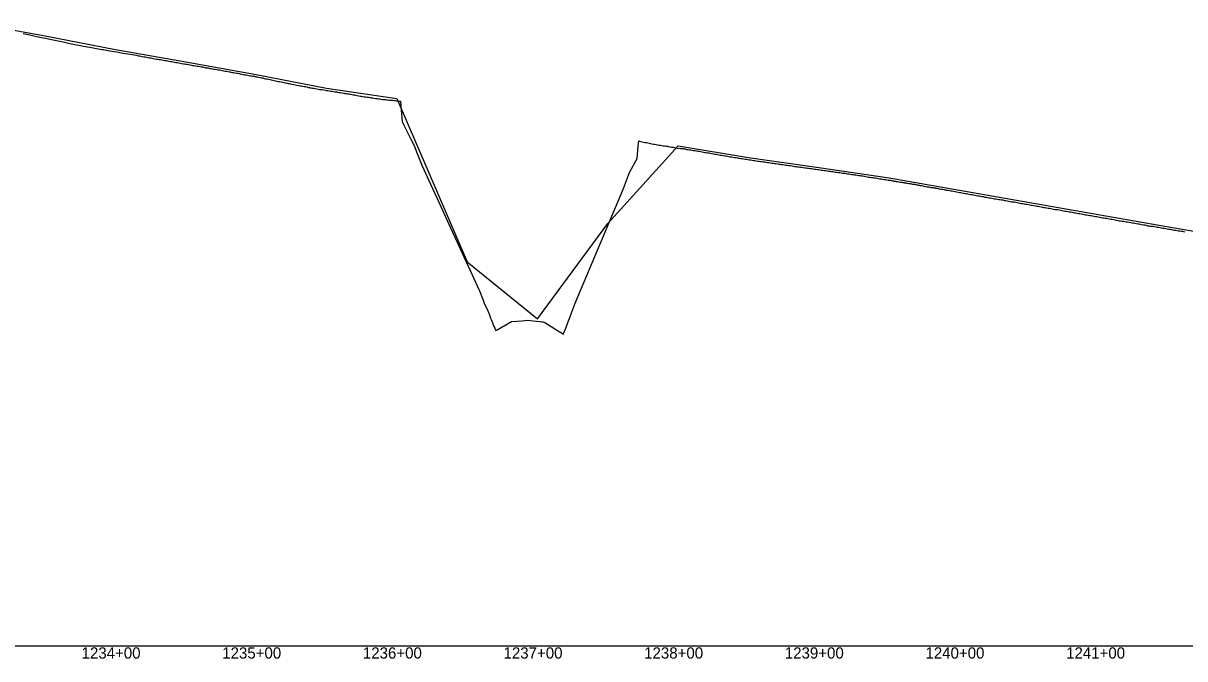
# Model space of a CAD drawing. Extents: x -3793 to 50787, y -1075 to 6138.
# Drawn here: x 10712 to 11538, y 2991 to 3442 of the extents above; entities that cross this region are included whole.
import ezdxf

# ---------------------------------------------------------------- set-up
doc = ezdxf.new("R2010")
doc.units = 0
for name, color, linetype in [('RD_DDB_Profile_EX', 7, 'Continuous'), ('RD_DDB_Profile_PR', 7, 'Continuous'), ('RD_DDB_StaTX', 7, 'Continuous'), ('RD_GPK_Profile_Cell', 7, 'Continuous')]:
    doc.layers.add(name, color=color, linetype=linetype)

msp = doc.modelspace()

# ---------------------------------------------------------------- linework, layer by layer
at = {"layer": 'RD_DDB_Profile_EX'}
for points in [[(10711.5226, 3435.037695), (10716.272076, 3434.033025), (10721.021552, 3433.02714), (10725.771029, 3432.020045), (10727.701013, 3431.648155), (10730.520505, 3431.05129), (10735.269982, 3430.04314), (10740.019458, 3429.03227), (10744.768934, 3428.01868), (10749.518411, 3427.00238), (10752.414609, 3426.418435), (10754.267887, 3426.09926), (10759.017363, 3425.277585), (10763.76684, 3424.452205), (10767.862399, 3423.713405), (10768.516316, 3423.602885), (10773.265792, 3422.797305), (10778.015269, 3421.98886), (10782.764745, 3421.17755), (10787.514221, 3420.36338), (10792.30311, 3419.57975), (10793.299339, 3419.285795), (10794.299228, 3419.14256), (10795.303154, 3418.943025), (10796.30302, 3418.74236), (10797.299199, 3418.58722), (10798.299138, 3418.43557), (10799.302349, 3418.18956), (10800.302281, 3417.99978), (10801.306182, 3417.80405), (10801.76265, 3417.758265), (10802.296945, 3417.704175), (10803.300912, 3417.483735), (10804.300165, 3417.34362), (10805.299063, 3417.053465), (10806.512127, 3416.93618), (10807.293775, 3416.84868), (10808.296695, 3416.689405), (10809.295635, 3416.499), (10810.299296, 3416.34801), (10811.289227, 3416.143485), (10812.292583, 3415.98803), (10813.291601, 3415.792745), (10814.293861, 3415.587365), (10815.29287, 3415.44605), (10816.287852, 3415.238785), (10817.285493, 3415.13517), (10818.288555, 3414.937095), (10819.28689, 3414.698905), (10820.236153, 3414.553075), (10820.760556, 3414.47179), (10821.232904, 3414.39124), (10822.230999, 3414.144775), (10823.222926, 3413.95443), (10824.221468, 3413.84666), (10825.510032, 3413.58003), (10826.221282, 3413.40868), (10827.21984, 3413.303775), (10828.219735, 3413.15324), (10829.225637, 3413.00416), (10830.259509, 3412.83919), (10831.2229, 3412.652015), (10832.215968, 3412.415745), (10833.215832, 3412.255615), (10834.221707, 3412.15596), (10835.214283, 3411.920275), (10836.219608, 3411.81587), (10837.219989, 3411.568015), (10838.218037, 3411.41629), (10839.217698, 3411.3046), (10839.758461, 3411.168325), (10840.215748, 3411.061815), (10841.215574, 3410.736265), (10842.215949, 3410.633465), (10843.213991, 3410.562915), (10844.507938, 3410.30062), (10845.219663, 3410.122675), (10846.212225, 3410.01766), (10847.217354, 3409.7752), (10848.209908, 3409.6658), (10849.257414, 3409.500895), (10850.215579, 3409.36089)], [(10850.215579, 3409.36089), (10851.208125, 3409.159955), (10852.213972, 3408.91263), (10853.213797, 3408.772075), (10854.211838, 3408.60583), (10855.211503, 3408.364145), (10856.204026, 3408.26264), (10857.209885, 3408.002185), (10858.20972, 3407.852405), (10858.756367, 3407.768325), (10859.207769, 3407.69868), (10860.208089, 3407.40217), (10861.213499, 3407.253535), (10862.20598, 3407.097785), (10863.505843, 3406.92422), (10864.203749, 3406.789215), (10865.204045, 3406.55249), (10865.999784, 3406.4476), (10867.057171, 3406.27399), (10868.255319, 3405.95116), (10868.979874, 3405.71299), (10869.981382, 3405.658365), (10871.057632, 3405.35229), (10871.977767, 3405.263525), (10873.061131, 3405.10046), (10874.065337, 3404.92293), (10874.981471, 3404.696475), (10876.064321, 3404.638615), (10876.977635, 3404.367665), (10877.972417, 3404.16866), (10878.973787, 3404.00678), (10880.062261, 3403.752835), (10880.970699, 3403.61878), (10881.972038, 3403.456255), (10882.503748, 3403.269245), (10883.063689, 3403.10206), (10883.968386, 3402.96807), (10885.061111, 3402.83864), (10885.96452, 3402.56961), (10887.253225, 3402.341515), (10887.960651, 3402.205725), (10889.056201, 3401.975375), (10889.957593, 3401.70641), (10890.958873, 3401.541925), (10892.055873, 3401.23155), (10892.955822, 3401.05243), (10893.95595, 3400.855115), (10895.057622, 3400.63565), (10896.05179, 3400.43008), (10896.953578, 3400.25052), (10897.954863, 3400.090495), (10898.43082, 3400), (10899.200461, 3399.766405), (10899.980789, 3399.649735), (10900.756284, 3399.49272), (10901.537873, 3399.37586), (10901.947913, 3399.288625), (10902.942719, 3399.16792), (10903.944035, 3398.882175), (10905.321318, 3398.572545), (10906.289417, 3398.434385), (10907.285695, 3398.18517), (10908.286228, 3397.993515), (10909.290089, 3397.890085), (10910.286909, 3397.696015), (10911.286863, 3397.4883), (10912.291126, 3397.30064), (10913.287248, 3397.09546), (10914.287728, 3396.80391), (10915.283841, 3396.615925), (10915.750083, 3396.570505), (10916.288006, 3396.487835), (10917.287768, 3396.25202), (10918.284402, 3396.145925), (10919.287844, 3395.95293), (10920.499559, 3395.674865), (10921.284159, 3395.517355), (10922.288121, 3395.367915), (10923.279311, 3395.25027), (10924.284325, 3395.157155), (10925.287587, 3395.00146), (10926.279366, 3394.83922), (10927.283602, 3394.65242), (10928.287439, 3394.49617), (10929.283221, 3394.31484), (10930.282738, 3394.12304), (10931.286477, 3393.97289), (10932.282174, 3393.80914), (10933.282317, 3393.710355), (10934.278008, 3393.50955), (10934.747988, 3393.46299), (10935.281708, 3393.402845), (10936.281067, 3393.24738), (10937.277375, 3393.059105), (10938.280349, 3392.921685), (10939.497465, 3392.70068), (10940.275954, 3392.490415), (10941.279549, 3392.426855), (10942.271456, 3392.23316), (10943.275053, 3392.08234), (10944.277978, 3391.956635)], [(10944.277978, 3391.956635), (10945.27047, 3391.68115), (10946.273334, 3391.574015), (10947.276886, 3391.422945), (10948.125354, 3391.223745), (10949.124194, 3391.036385), (10950.122287, 3390.855175), (10951.148796, 3390.59418), (10952.148343, 3390.44546), (10953.142979, 3390.32913), (10954.142482, 3390.09315), (10955.141247, 3389.994275), (10956.140658, 3389.875385), (10957.148192, 3389.713985), (10958.147617, 3389.57145), (10958.49537, 3389.501975), (10959.146274, 3389.372215), (10960.145539, 3389.265875), (10961.139915, 3389.1315), (10962.146749, 3388.939905), (10963.244846, 3388.77369), (10964.145717, 3388.676975), (10965.14415, 3388.54154), (10966.143276, 3388.39177), (10967.149238, 3388.26466), (10968.148342, 3388.222045), (10969.146607, 3388.136565), (10970.142673, 3388.010195), (10971.140938, 3387.99669), (10972.147425, 3387.81277), (10973.145623, 3387.75551), (10974.14443, 3387.69941), (10975.142528, 3387.48992), (10976.142609, 3387.381435), (10977.148226, 3387.203235), (10977.493275, 3387.1688), (10978.142782, 3387.104045), (10979.140709, 3387.06081), (10979.998327, 3387.024545), (10980.478464, 3380.58499), (10980.995674, 3372.54904), (10982.242752, 3370.042175), (10986.992228, 3360.49365), (10989.273855, 3355.906035), (10991.741705, 3349.777605), (10995.093873, 3341.451325), (10996.491181, 3338.414105), (11001.240657, 3328.08981), (11005.990134, 3317.764805), (11010.73961, 3307.439125), (11015.489086, 3297.112795), (11020.238563, 3286.78585), (11024.988039, 3276.45831), (11029.737515, 3266.130215), (11034.486992, 3255.801585), (11036.158402, 3252.166615), (11038.785117, 3245.509115), (11039.236468, 3244.248405), (11039.723685, 3242.888265), (11040.757161, 3240.529295), (11041.868532, 3238.03651), (11043.09915, 3235.14413), (11043.985944, 3232.84878), (11044.353961, 3231.89664), (11045.337396, 3229.568125), (11046.313644, 3226.949935), (11046.96272, 3225.75562), (11047.750403, 3224.08031), (11048.735421, 3224.659325), (11052.713079, 3226.998465), (11053.484897, 3227.4145), (11056.083854, 3228.815255), (11058.928951, 3230.36871), (11062.518094, 3230.696995), (11066.057082, 3231.0213), (11068.206228, 3231.208645), (11070.404375, 3231.419235), (11074.150154, 3230.998715), (11079.0208, 3230.45052), (11080.237702, 3230.313655), (11081.180516, 3230.20771), (11082.440301, 3229.869885), (11089.630611, 3225.29527), (11095.721485, 3221.48838), (11096.089507, 3222.43014), (11097.446264, 3225.824595), (11098.664693, 3229.068585), (11099.788999, 3232.04427), (11103.424789, 3241.514595), (11104.174874, 3243.540475), (11138.549471, 3324.95213), (11142.802066, 3336.407525), (11148.165449, 3346.339715), (11148.874291, 3354.928305), (11149.230024, 3358.743785), (11149.561851, 3358.646965), (11150.691356, 3358.433315), (11151.690668, 3358.183495), (11152.693441, 3357.896705), (11153.684135, 3357.706675), (11154.688151, 3357.576625)], [(11154.688151, 3357.576625), (11155.687467, 3357.39685), (11156.689704, 3357.240055), (11157.684389, 3356.89625), (11158.684944, 3356.64655), (11159.687186, 3356.533165), (11160.553298, 3356.35998), (11161.682409, 3356.24625), (11162.681208, 3356.009885), (11163.551638, 3355.83608), (11164.678636, 3355.676225), (11165.678671, 3355.50288), (11166.681439, 3355.372405), (11167.548557, 3355.24261), (11168.675414, 3355.015495), (11169.675456, 3354.92924), (11170.546896, 3354.79856), (11171.672856, 3354.51505), (11172.671673, 3354.315525), (11173.675664, 3354.26531), (11174.543814, 3354.048455), (11175.669112, 3353.95206), (11176.668449, 3353.71309), (11177.672436, 3353.45219), (11178.540733, 3353.495895), (11178.863948, 3353.479455), (11179.71095, 3353.30824), (11180.568666, 3353.265185), (11181.303162, 3353.11465), (11182.307317, 3353.01467), (11183.298534, 3352.7), (11184.301413, 3352.585265), (11185.305571, 3352.49262), (11186.304188, 3352.4), (11187.300959, 3352.170315), (11188.299591, 3352.027495), (11189.301702, 3351.88496), (11190.298487, 3351.785035), (11191.297115, 3351.492435), (11192.301285, 3351.362105), (11193.299912, 3351.15), (11194.295396, 3351.05), (11195.299569, 3350.84237), (11196.298201, 3350.634565), (11197.301037, 3350.484555), (11198.292897, 3350.32665), (11199.295725, 3350.18442), (11200.299907, 3349.942195), (11201.298534, 3349.718415), (11202.387926, 3349.57648), (11203.388252, 3349.37625), (11204.390252, 3349.31841), (11205.393751, 3349.152665), (11206.386102, 3348.902535), (11207.38869, 3348.73425), (11208.389038, 3348.568185), (11209.392536, 3348.426165), (11210.386531, 3348.23426), (11211.386894, 3348.034105), (11212.39039, 3347.88412), (11213.381839, 3347.760325), (11214.385333, 3347.55244), (11215.388825, 3347.41041), (11216.387705, 3347.252075), (11217.38318, 3347.068315), (11218.383597, 3346.90999), (11219.385564, 3346.76807), (11220.229469, 3346.6), (11220.870179, 3346.56812), (11221.869667, 3346.367795), (11222.867744, 3346.17563), (11223.867242, 3345.97538), (11224.866753, 3345.866835), (11225.864811, 3345.69982), (11226.865155, 3345.51628), (11227.864696, 3345.38297), (11228.866784, 3345.224505), (11229.866321, 3345.07425), (11230.865871, 3344.906645), (11231.8639, 3344.815015), (11232.863462, 3344.60583), (11233.871105, 3344.432075), (11234.869105, 3344.33192), (11235.868687, 3344.222615), (11236.868283, 3344.08156), (11237.870234, 3343.940795), (11238.869826, 3343.790705), (11239.870342, 3343.690635), (11240.868312, 3343.53111), (11241.867936, 3343.34046), (11242.827964, 3343.15), (11243.828254, 3343.059665), (11244.826916, 3342.880555), (11245.825578, 3342.8), (11246.82424, 3342.60984), (11247.826118, 3342.5), (11248.826444, 3342.320305), (11249.825104, 3342.190045), (11250.823764, 3342.05), (11251.822424, 3341.91007), (11252.821083, 3341.779745)], [(11252.821083, 3341.779745), (11253.828223, 3341.620525), (11254.826883, 3341.46032), (11255.824439, 3341.35), (11256.827306, 3341.2), (11258.271562, 3340.989525), (11259.271035, 3340.8), (11260.270507, 3340.66059), (11261.26998, 3340.489355), (11262.269452, 3340.35), (11263.270981, 3340.23922), (11264.269672, 3340.06741), (11265.269152, 3340.01092), (11266.268631, 3339.88902), (11267.275539, 3339.738905), (11268.275008, 3339.55), (11269.276617, 3339.47754), (11270.276097, 3339.37742), (11271.275576, 3339.2), (11272.274219, 3339.05), (11273.273695, 3338.95), (11274.275377, 3338.761565), (11275.274863, 3338.65), (11276.27435, 3338.45), (11277.273836, 3338.338255), (11278.273322, 3338.2764), (11279.275079, 3338.01188), (11280.281852, 3337.87399), (11281.280458, 3337.786245), (11282.27994, 3337.66214), (11283.282189, 3337.47578), (11284.283994, 3337.375625), (11285.283483, 3337.313265), (11286.287691, 3337.11297), (11287.28631, 3336.97514), (11288.288215, 3336.8), (11289.286832, 3336.662205), (11290.287873, 3336.51271), (11291.28648, 3336.4256), (11292.28847, 3336.28712), (11293.296682, 3336.1), (11294.295269, 3335.91314), (11295.296387, 3335.786745), (11295.706357, 3335.75), (11296.702402, 3335.56321), (11297.70228, 3335.439975), (11298.705759, 3335.31335), (11299.70462, 3335.2), (11300.704521, 3334.963525), (11301.705629, 3334.827065), (11302.699162, 3334.72718), (11303.70159, 3334.55), (11304.701506, 3334.45), (11305.701441, 3334.2914), (11306.702497, 3334.127615), (11307.703786, 3333.95557), (11308.704824, 3333.8417), (11309.698455, 3333.641885), (11310.701927, 3333.44198), (11311.700801, 3333.30623), (11312.700777, 3333.06418), (11313.701759, 3333.02838), (11314.703124, 3332.79284), (11315.697828, 3332.67114), (11316.697823, 3332.52178), (11317.70129, 3332.421955), (11318.70017, 3332.23674), (11319.70019, 3332.09376), (11320.701094, 3331.908395), (11321.70111, 3331.79419), (11322.697231, 3331.55856), (11323.697271, 3331.42955), (11324.700734, 3331.329625), (11325.699621, 3331.194645), (11326.699688, 3330.96007), (11327.700509, 3330.860125), (11328.398137, 3330.755555), (11328.727924, 3330.695325), (11329.7239, 3330.44505), (11330.421897, 3330.340395), (11330.724297, 3330.234955), (11331.72652, 3330.080035), (11332.424528, 3329.975325), (11333.018039, 3329.940345), (11333.319138, 3329.880155), (11334.016473, 3329.775635), (11334.319858, 3329.73021), (11335.314757, 3329.53994), (11336.013378, 3329.434935), (11336.314595, 3329.45), (11337.015833, 3329.24021), (11337.316486, 3329.19517), (11338.014271, 3329.125525), (11338.316319, 3329.08025), (11339.016724, 3328.94046), (11339.319099, 3328.88011), (11340.011169, 3328.775205), (11340.311938, 3328.7), (11341.310819, 3328.56999), (11342.009598, 3328.43011), (11342.310648, 3328.415075)], [(11342.310648, 3328.415075), (11343.012061, 3328.310105), (11343.312543, 3328.219905), (11344.004769, 3328.080065), (11344.306261, 3328.06501), (11345.308154, 3327.935015), (11346.007394, 3327.76013), (11346.307993, 3327.7), (11347.009857, 3327.59501), (11347.309885, 3327.55), (11348.008282, 3327.4103), (11348.30972, 3327.365095), (11349.005027, 3327.259925), (11349.305482, 3327.17008), (11350.005187, 3327.06501), (11350.305332, 3327.03497), (11351.307221, 3326.854995), (11352.00608, 3326.54031), (11352.307066, 3326.525365), (11353.004508, 3326.45586), (11353.307794, 3326.35), (11354.302664, 3326.219985), (11355.001418, 3326.15), (11355.302523, 3326.11984), (11356.003876, 3325.945085), (11356.304405, 3325.91505), (11357.002307, 3325.7057), (11357.304261, 3325.660485), (11357.999044, 3325.62503), (11358.299989, 3325.594955), (11358.99921, 3325.52517), (11359.299859, 3325.465055), (11360.001669, 3325.36002), (11360.301738, 3325.269945), (11361.000104, 3325.130155), (11361.301604, 3325.0849), (11362.002562, 3325.01505), (11362.303483, 3324.96986), (11362.995274, 3324.690325), (11363.297188, 3324.66013), (11364.299064, 3324.49501), (11364.997899, 3324.42527), (11365.29894, 3324.365075), (11366.297795, 3324.21502), (11366.990607, 3324.11001), (11367.290629, 3324.034975), (11367.993075, 3323.82487), (11368.29337, 3323.76495), (11369.193142, 3323.684985), (11370.194703, 3323.514875), (11371.192429, 3323.385125), (11372.189034, 3323.179475), (11373.186775, 3323.029475), (11374.187253, 3322.8), (11375.28425, 3322.59362), (11376.282005, 3322.320915), (11377.282798, 3322.17889), (11378.276693, 3322.043225), (11379.277501, 3321.828625), (11380.275278, 3321.664315), (11381.277354, 3321.320895), (11382.277735, 3321.36421), (11383.272049, 3321.106195), (11384.269851, 3320.928105), (11385.273311, 3320.763985), (11386.272322, 3320.6), (11387.266653, 3320.427585), (11388.267001, 3320.277645), (11389.267946, 3320.07746), (11390.265778, 3319.80494), (11391.263786, 3319.740695), (11392.261634, 3319.53643), (11393.259481, 3319.204315), (11394.26049, 3319.176975), (11395.260802, 3318.85407), (11396.256321, 3318.75), (11397.254191, 3318.636665), (11398.257666, 3318.40307), (11399.255541, 3318.25), (11400.249921, 3318.136875), (11401.250201, 3317.88946), (11402.252432, 3317.678185), (11403.250329, 3317.56304), (11404.253817, 3317.4), (11405.244981, 3317.22584), (11406.246128, 3317.024335), (11407.245164, 3316.9), (11408.24866, 3316.8), (11409.239809, 3316.50076), (11410.241007, 3316.32521), (11411.241232, 3316.187905), (11412.270572, 3316.06251), (11413.262888, 3315.82503), (11414.263934, 3315.537), (11415.264213, 3315.47492), (11416.265277, 3315.362375), (11417.265549, 3315.174815), (11418.259658, 3314.89904), (11419.314207, 3314.79913), (11420.305281, 3314.61223), (11421.307684, 3314.398795)], [(11421.307684, 3314.398795), (11422.305665, 3314.236635), (11423.309122, 3314.09859), (11424.300189, 3313.84839), (11425.30364, 3313.712035), (11426.301637, 3313.6), (11427.305094, 3313.311985), (11428.303095, 3313.161995), (11429.29858, 3313.023805), (11430.296589, 3312.861915), (11431.300052, 3312.597405), (11432.298064, 3312.485595), (11433.294557, 3312.28522), (11434.29473, 3312.161775), (11435.296045, 3311.985075), (11436.29621, 3311.785175), (11437.28954, 3311.56161), (11438.289698, 3311.461645), (11439.291045, 3311.31156), (11440.291196, 3311.034785), (11441.285537, 3310.911455), (11442.285681, 3310.77297), (11443.287058, 3310.538595), (11444.287195, 3310.32288), (11445.287601, 3310.145545), (11446.280691, 3310.034075), (11447.282098, 3309.91128), (11448.282221, 3309.722625), (11449.280283, 3309.538675), (11450.276694, 3309.283615), (11451.274767, 3308.98976), (11452.278239, 3308.92232), (11453.275344, 3308.7612), (11454.271744, 3308.62216), (11455.382957, 3308.45), (11456.385126, 3308.261085), (11457.384879, 3308.144265), (11458.38774, 3307.922405), (11459.158416, 3307.65), (11459.929866, 3307.561015), (11460.932525, 3307.46098), (11461.931425, 3307.28896), (11462.927222, 3307.15), (11463.930938, 3306.87177), (11464.929843, 3306.72811), (11465.925625, 3306.471695), (11466.928297, 3306.35), (11467.928245, 3306.260845), (11468.924011, 3306.042995), (11469.924807, 3305.82861), (11470.916795, 3305.689305), (11471.919483, 3305.471315), (11472.9232, 3305.181785), (11473.915171, 3305.08178), (11474.917865, 3304.95), (11475.920567, 3304.73948), (11476.912524, 3304.6), (11477.916231, 3304.410455), (11478.911961, 3304.14142), (11479.910879, 3304.08125), (11480.913588, 3303.91038), (11481.909313, 3303.760275), (11482.909217, 3303.52937), (11483.911933, 3303.410275), (11484.90585, 3303.189845), (11485.904761, 3303.06022), (11486.90847, 3302.840625), (11487.904179, 3302.75), (11488.903095, 3302.55), (11489.898791, 3302.3), (11490.901538, 3302.079915), (11491.901412, 3301.93999), (11492.897091, 3301.8), (11493.899845, 3301.690135), (11494.898765, 3301.54007), (11495.89444, 3301.30982), (11496.898134, 3301.15), (11498.084495, 3300.99025), (11499.082949, 3300.790225), (11500.083358, 3300.55), (11501.083772, 3300.44015), (11502.076535, 3300.261185), (11503.076945, 3300.04026), (11504.074824, 3299.76958), (11505.075233, 3299.74017), (11506.076064, 3299.54025), (11507.076465, 3299.430425), (11508.074909, 3299.23038), (11509.075311, 3299.030305), (11510.078107, 3298.8913), (11511.07596, 3298.54017), (11512.076358, 3298.470395), (11513.074786, 3298.3), (11514.077599, 3298.240175), (11515.068024, 3298.07065), (11516.068418, 3297.93036), (11517.068817, 3297.64014), (11518.069075, 3297.53039), (11519.069465, 3297.370475), (11520.067894, 3297.130275), (11521.068284, 3297.0302)], [(11521.068284, 3297.0302), (11522.069147, 3296.880355), (11523.069531, 3296.7), (11524.069918, 3296.44062), (11524.870833, 3296.360215), (11526.070565, 3296.11976), (11527.068981, 3296.030195), (11528.061393, 3295.85), (11528.86275, 3295.649615), (11530.062649, 3295.440165), (11531.063029, 3295.280255), (11532.061447, 3295.180215), (11533.061219, 3294.95995), (11534.0621, 3294.83025), (11535.062473, 3294.65), (11535.863082, 3294.52988), (11536.652242, 3294.36991), (11537.652092, 3294.15)]]:
    msp.add_lwpolyline(points, dxfattribs=at)
at = {"layer": 'RD_DDB_Profile_PR'}
msp.add_lwpolyline([(10677.33, 3442.337), (10727.33, 3433.3195), (10777.33, 3423.7055), (10827.33, 3414.887), (10877.33, 3405.897), (10927.33, 3396.245), (10977.33, 3388.785), (11027.33, 3272.9655), (11077.33, 3232.241), (11127.33, 3299.9805), (11177.33, 3355.141), (11227.33, 3347.0545), (11277.33, 3339.935), (11327.33, 3332.497), (11377.33, 3323.7725), (11427.33, 3314.908), (11477.33, 3306.121), (11527.33, 3297.583), (11577.33, 3288.9115)], dxfattribs=at)
at = {"layer": 'RD_GPK_Profile_Cell'}
msp.add_line((1000, 3000), (46549.603806, 3000), dxfattribs=at)

# ---------------------------------------------------------------- texts
at = {"layer": 'RD_DDB_StaTX'}
for s, p in [('1234+00', (10753.125471, 2991)), ('1234+00', (10753.125471, 2991)), ('1235+00', (10853.125471, 2991)), ('1235+00', (10853.125471, 2991)), ('1236+00', (10953.125471, 2991)), ('1236+00', (10953.125471, 2991)), ('1237+00', (11053.125471, 2991)), ('1237+00', (11053.125471, 2991)), ('1238+00', (11153.125471, 2991)), ('1238+00', (11153.125471, 2991)), ('1239+00', (11253.125471, 2991)), ('1239+00', (11253.125471, 2991)), ('1240+00', (11353.125471, 2991)), ('1240+00', (11353.125471, 2991)), ('1241+00', (11453.125471, 2991)), ('1241+00', (11453.125471, 2991))]:
    msp.add_text(s, height=8, dxfattribs=at).set_placement(p)

doc.saveas('drawing.dxf')
